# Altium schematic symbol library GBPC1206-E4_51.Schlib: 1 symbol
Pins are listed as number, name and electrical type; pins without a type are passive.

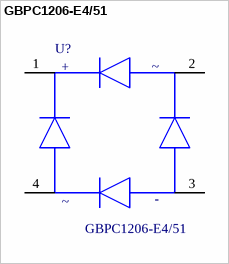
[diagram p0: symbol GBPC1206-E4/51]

## GBPC1206-E4/51
designator U?
DISCRETE, RECTIFIER BRIDGE 12A 600V, GBPC-4; Manufacturer: VISHAY SEMICONDUCTOR; SymbolCreator: X0199378
pins: 1, 2, 3, 4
